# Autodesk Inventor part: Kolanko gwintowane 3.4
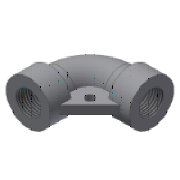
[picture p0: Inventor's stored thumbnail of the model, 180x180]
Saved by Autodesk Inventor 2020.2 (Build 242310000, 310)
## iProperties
IsCustomPart: 0
Manager: www.cadconsulting.pl
Company: Fabian Stasiak CAD Consulting
Created: 2014-08
Part Number: Kolanko gwintowane 3.4
Material: Ogólny
Document SubType Name: Modeling
Designer: F.Stasiak
Standards Organization: ANSI
Language: pl-PL
Size Designation: 3/4
Categories: <MemberInstance><Categories><Category DisplayName="Rury cienko- i grubościenne" InternalName="4347fa0f-2144-441d-94cd-e3e15c92b736" Mnemonic="TUBEANDPIPE"><Cate
Density: 1 g/cm^3
Appearance: Domyślna
Catalog Web Link: www.expertbooks.pl
Author: F.Stasiak
Subject: Zbiór ćwiczeń. Autodesk Inventor 2020. Kurs Professional
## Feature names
1. Przeciągnięcie1
2. Wyciągnięcie proste1 [Extrusion]
3. Wyciągnięcie proste2 [Extrusion]
4. Wyciągnięcie proste5 [Extrusion]
## Parameters: d0 = 59.182 mm, d1 = 59.182 mm, d2 = 29.591 mm, d4 = 0, d5 = 0, d6 = 38.1 mm, d7 = 23.6728 mm, d9 = 18.3134 mm, d10 = 0, d11 = 38.1 mm, d12 = 18.3134 mm, d13 = 0, d19 = 19.8628 mm, d20 = 0, d21 = 19.8628 mm, d22 = 0, ID = 23.6728 mm, OD = 38.1 mm, GL = 18.3134 mm, G = 3.429 mm, d23 = 3.429 mm, d24 = 6.35 mm, d26 = 6.858 mm, d27 = 0
